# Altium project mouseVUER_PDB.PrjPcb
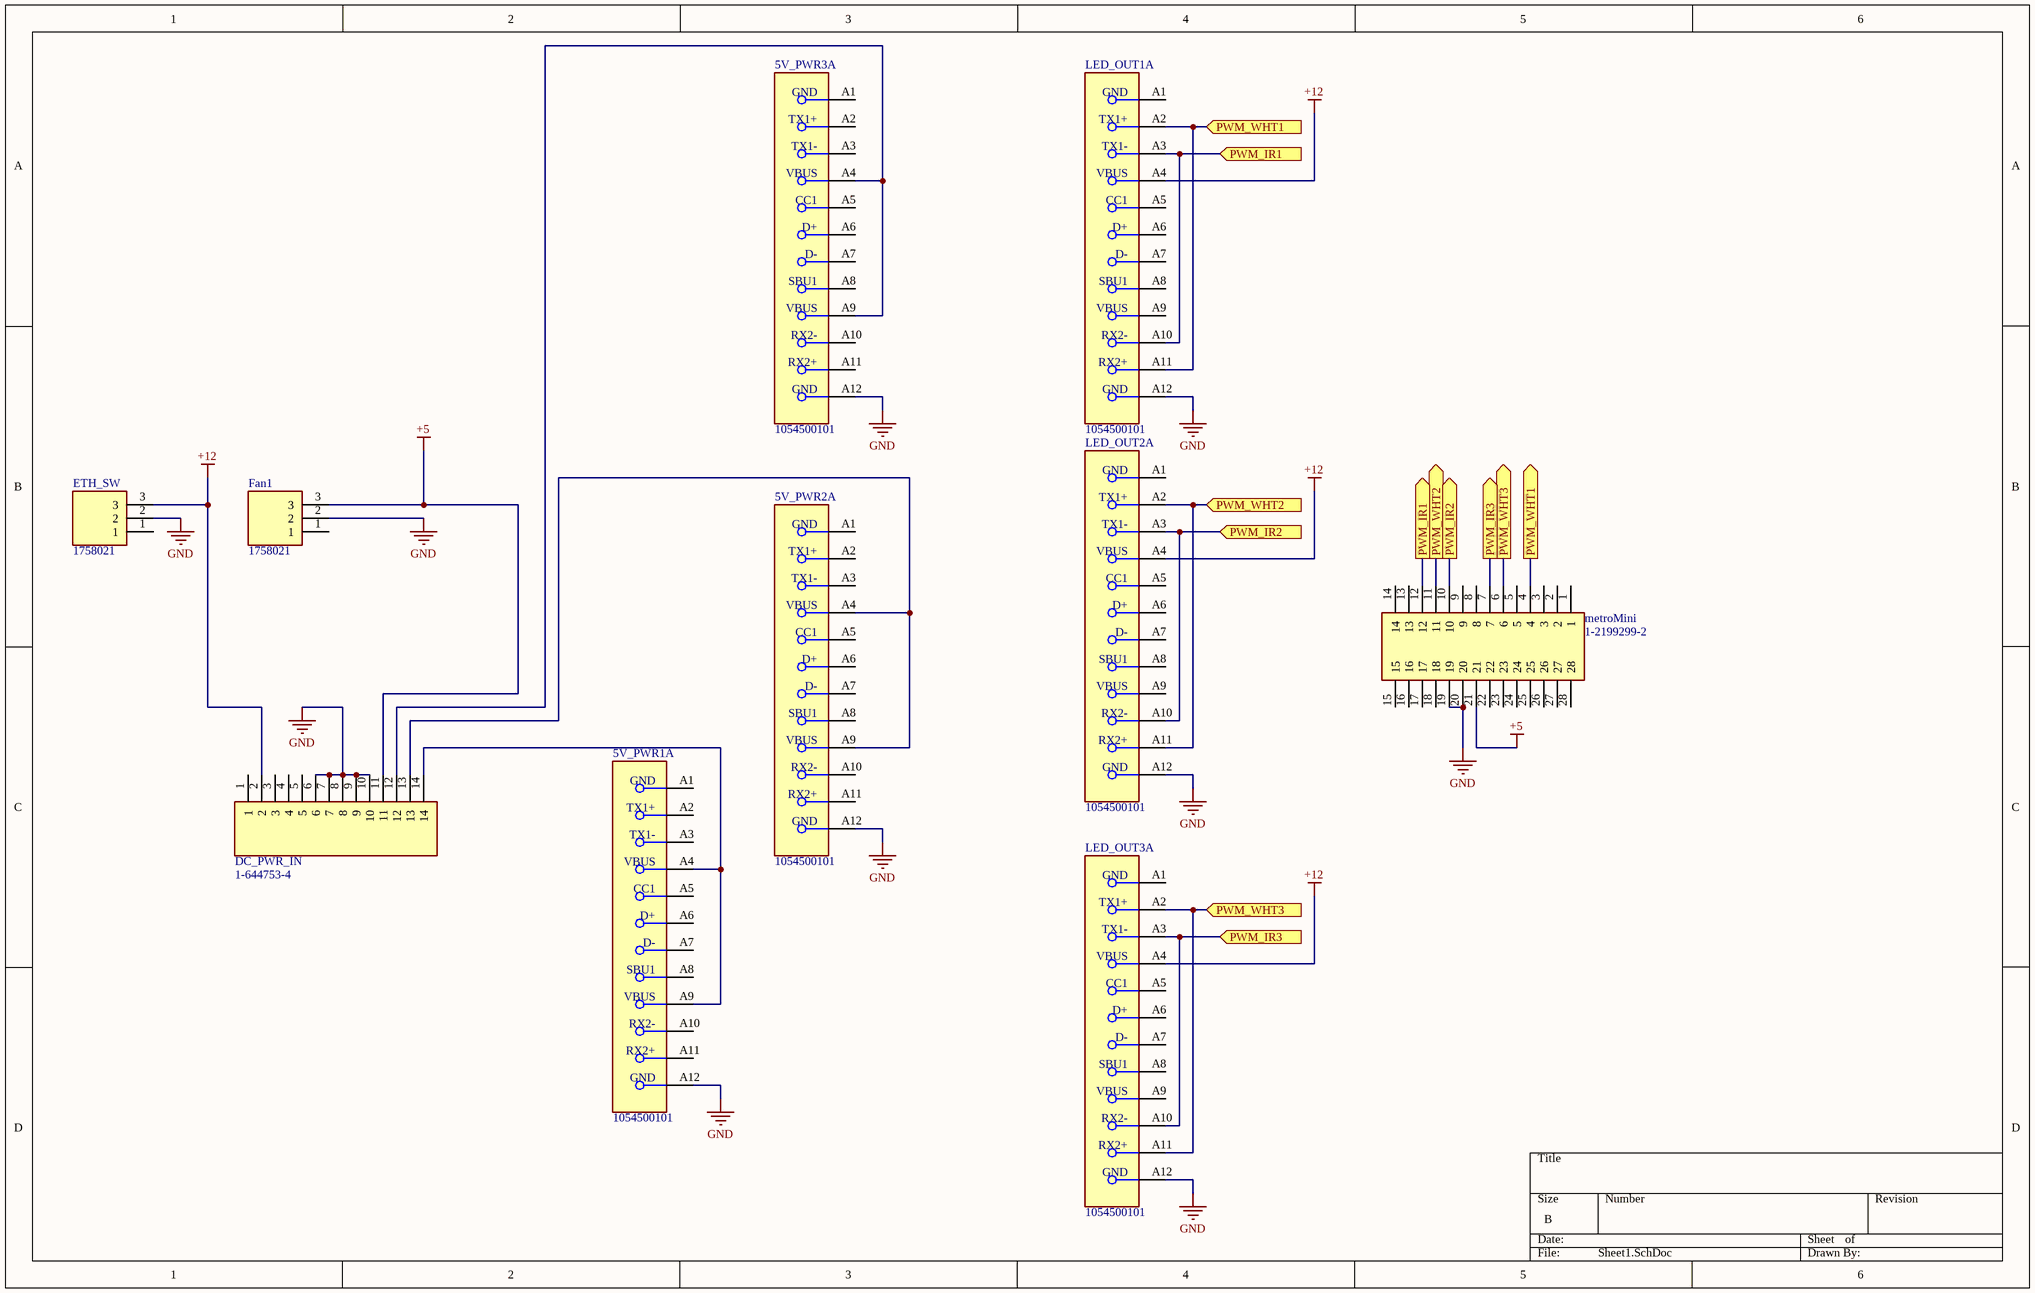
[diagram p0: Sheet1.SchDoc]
1 sheet, 10 parts. Net scope: flat (ports and power ports of the same name join across sheets).
Board file: PCB1.PcbDoc

## Sheet Sheet1.SchDoc
size B; SheetNumber: 1; SheetTotal: 1

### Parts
5V_PWR1  1054500101  [FP-1054500101-MFG]  (part A of 3)
5V_PWR2  1054500101  [FP-1054500101-MFG]  (part A of 3)
5V_PWR3  1054500101  [FP-1054500101-MFG]  (part A of 3)
DC_PWR_IN  1-644753-4  [16447534]
ETH_SW  1758021  [1758021]
Fan1  1758021  [1758021]
LED_OUT1  1054500101  [FP-1054500101-MFG]  (part A of 3)
LED_OUT2  1054500101  [FP-1054500101-MFG]  (part A of 3)
LED_OUT3  1054500101  [FP-1054500101-MFG]  (part A of 3)
metroMini  1-2199299-2  [DIPS1524W70P254L3556H530Q28N]

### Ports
PWM_IR1 (in, see Sheet1[5B]), PWM_IR1 (out, see Sheet1[4A]), PWM_IR2 (in, see Sheet1[5B]), PWM_IR2 (out, see Sheet1[4B]), PWM_IR3 (in, see Sheet1[5B]), PWM_IR3 (out, see Sheet1[4C]), PWM_WHT1 (in, see Sheet1[5B]), PWM_WHT1 (out, see Sheet1[4A]), PWM_WHT2 (in, see Sheet1[5B]), PWM_WHT2 (out, see Sheet1[4B]), PWM_WHT3 (in, see Sheet1[5B]), PWM_WHT3 (out, see Sheet1[4C])

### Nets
+5: DC_PWR_IN.11 Fan1.3 metroMini.21
+12: DC_PWR_IN.2 ETH_SW.3 LED_OUT1.A4(VBUS) LED_OUT2.A4(VBUS) LED_OUT3.A4(VBUS)
GND: 5V_PWR1.A12(GND) 5V_PWR2.A12(GND) 5V_PWR3.A12(GND) DC_PWR_IN.6 DC_PWR_IN.7 DC_PWR_IN.8 DC_PWR_IN.9 DC_PWR_IN.10 ETH_SW.2 Fan1.2 LED_OUT1.A12(GND) LED_OUT2.A12(GND) LED_OUT3.A12(GND) metroMini.19 metroMini.20
Net5V_PWR1_A4: 5V_PWR1.A4(VBUS) 5V_PWR1.A9(VBUS) DC_PWR_IN.14
Net5V_PWR2_A4: 5V_PWR2.A4(VBUS) 5V_PWR2.A9(VBUS) DC_PWR_IN.13
Net5V_PWR3_A4: 5V_PWR3.A4(VBUS) 5V_PWR3.A9(VBUS) DC_PWR_IN.12
NetLED_OUT1_A2: LED_OUT1.A2(TX1+) LED_OUT1.A11(RX2+) metroMini.4 ; port PWM_WHT1
NetLED_OUT1_A3: LED_OUT1.A3(TX1-) LED_OUT1.A10(RX2-) metroMini.12 ; port PWM_IR1
NetLED_OUT2_A2: LED_OUT2.A2(TX1+) LED_OUT2.A11(RX2+) metroMini.11 ; port PWM_WHT2
NetLED_OUT2_A3: LED_OUT2.A3(TX1-) LED_OUT2.A10(RX2-) metroMini.10 ; port PWM_IR2
NetLED_OUT3_A2: LED_OUT3.A2(TX1+) LED_OUT3.A11(RX2+) metroMini.6 ; port PWM_WHT3
NetLED_OUT3_A3: LED_OUT3.A3(TX1-) LED_OUT3.A10(RX2-) metroMini.7 ; port PWM_IR3

Not connected (* = marked no-connect by the designer): 5V_PWR1 A1(GND) A2(TX1+) A3(TX1-) A5(CC1) A6(D+) A7(D-) A8(SBU1) A10(RX2-) A11(RX2+); 5V_PWR2 A1(GND) A2(TX1+) A3(TX1-) A5(CC1) A6(D+) A7(D-) A8(SBU1) A10(RX2-) A11(RX2+); 5V_PWR3 A1(GND) A2(TX1+) A3(TX1-) A5(CC1) A6(D+) A7(D-) A8(SBU1) A10(RX2-) A11(RX2+); DC_PWR_IN 1 3 4 5; ETH_SW 1; Fan1 1; LED_OUT1 A1(GND) A5(CC1) A6(D+) A7(D-) A8(SBU1) A9(VBUS); LED_OUT2 A1(GND) A5(CC1) A6(D+) A7(D-) A8(SBU1) A9(VBUS); LED_OUT3 A1(GND) A5(CC1) A6(D+) A7(D-) A8(SBU1) A9(VBUS); metroMini 1 2 3 5 8 9 13 14 15 16 17 18 22 23 24 25 26 27 28

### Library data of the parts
5V_PWR1-5V_PWR3 LED_OUT1-LED_OUT3 = CMP-04767-000004-1: CONN RCP USB3.1 TYPEC 24P SMD RA; Manufacturer: Molex; Number Of Contacts: 24; Voltage Rating: 30V; Shielding: true; Is Female: yes; Current Rating: 0.25/1.25/5A; Pitch: 0.5mm; Conn Orientation: Right Angle
DC_PWR_IN = 1-644753-4: Headers & Wire Housings 14P HDR RN STR F/L; Manufacturer_Name: TE Connectivity; Geometry.Height: 13.589mm
ETH_SW Fan1 = 1758021: PCB header, nominal cross section: 2.5 mm?, color: green, nominal current: 12 A, rated voltage (III/2): 320 V, contact surface: Tin, type of contact: Male connector, Number of potentials: 3, Number of rows: 1, Number of positions per row: 3, number of connections: 3, product range: MSTBV 2,5/..-G, pitch: 5.08 mm, mounting: Wave soldering, pin layout: Linear pinning, solder pin [P]: 3.9 mm, Stecksystem: CLASSIC COMBICON, Locking: without, type of packaging: packed in cardboard; Manufacturer_Name: Phoenix Contact; Geometry.Height: 12.15mm
metroMini = 1-2199299-2: TE CONNECTIVITY - 1-2199299-2 - IC SOCKET, DIP, 28POS, TH; Geometry.Height: 5.3mm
